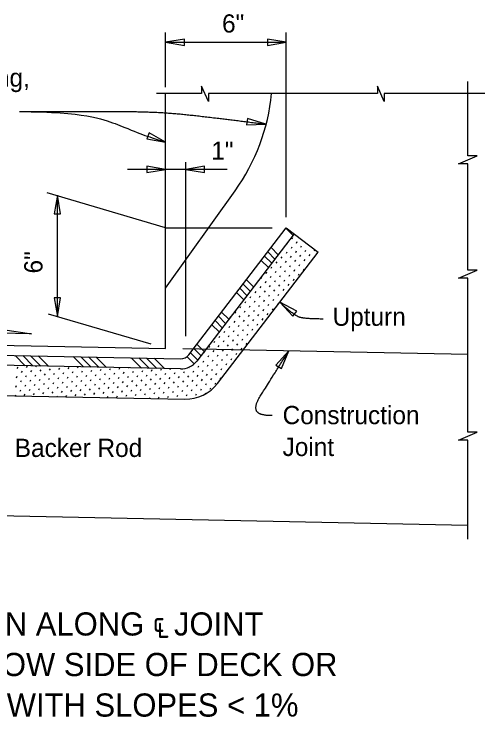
# Model space of a CAD drawing. Extents: x -7.9 to 27, y -3.1 to 14.6.
# Drawn here: x 12.683 to 14.635, y 7.031 to 9.943 of the extents above; entities that cross this region are included whole.
import ezdxf

# ---------------------------------------------------------------- set-up
doc = ezdxf.new("R2010")
doc.units = 0
for name, color, linetype in [('Border', 7, 'Continuous'), ('Patterning', 7, 'Continuous'), ('PlotBorder_dp', 7, 'Continuous'), ('SupstrConc_h', 7, 'Continuous'), ('TextMisc', 7, 'Continuous')]:
    doc.layers.add(name, color=color, linetype=linetype)

msp = doc.modelspace()

# ---------------------------------------------------------------- linework, layer by layer
at = {"layer": 'Patterning'}
for p, q in [((13.3108, 8.8076), (13.3108, 9.6137)), ((13.3108, 8.8076), (13.5991, 9.2112)), ((13.3108, 8.5576), (13.3108, 8.8076)), ((11.429, 8.5953), (13.3109, 8.5576)), ((14.5636, 7.8243), (11.2433, 7.8907))]:
    msp.add_line(p, q, dxfattribs=at)
msp.add_arc((12.9211, 9.6955), 0.8333, 324.4623, 354.3636, dxfattribs=at)
at = {"layer": 'PlotBorder_dp'}
for p, q in [((13.3108, 9.6403), (13.3108, 9.8663)), ((13.8108, 9.101), (13.8108, 9.8663)), ((13.3109, 9.8265), (13.8108, 9.8265)), ((13.3943, 8.6086), (13.3943, 9.3289)), ((13.5659, 9.2993), (13.1524, 9.2993)), ((13.3108, 9.0576), (12.8193, 9.202)), ((12.8626, 8.6893), (12.8626, 9.1931)), ((13.3108, 9.0576), (13.7523, 9.0576)), ((13.2505, 8.5753), (12.8258, 8.7001))]:
    msp.add_line(p, q, dxfattribs=at)
for points in [[(13.3108, 9.8265), (13.3889, 9.8133), (13.3889, 9.8398)], [(13.8108, 9.8265), (13.7327, 9.8398), (13.7327, 9.8133)], [(13.7257, 9.487), (13.65, 9.5101), (13.6466, 9.4839)], [(13.3108, 9.4117), (13.2421, 9.4512), (13.233, 9.4263)], [(13.3108, 9.2993), (13.2327, 9.3125), (13.2327, 9.2861)], [(13.3941, 9.2993), (13.4722, 9.2861), (13.4722, 9.3125)], [(12.8625, 9.1931), (12.8493, 9.115), (12.8757, 9.115)], [(12.8625, 8.6893), (12.8757, 8.7674), (12.8493, 8.7674)], [(13.7846, 8.7493), (13.8388, 8.6916), (13.8548, 8.7127)], [(13.8212, 8.5474), (13.7685, 8.4883), (13.7909, 8.4742)]]:
    msp.add_lwpolyline(points, close=True, dxfattribs=at)
for points in [[(14.0016, 9.6137), (13.4885, 9.6137), (13.4885, 9.5806), (13.4602, 9.6446), (13.4602, 9.6137), (13.2727, 9.6137)], [(14.6346, 9.6137), (14.2175, 9.6137), (14.2175, 9.5806), (14.1891, 9.6446), (14.1891, 9.6137), (14.0016, 9.6137)], [(14.5635, 9.1117), (14.5635, 9.3223), (14.5248, 9.3223), (14.5635, 9.3391), (14.6023, 9.356), (14.5635, 9.356), (14.5635, 9.6632)], [(14.5635, 8.5716), (14.5635, 8.8485), (14.5248, 8.8485), (14.5635, 8.8654), (14.6023, 8.8823), (14.5635, 8.8823), (14.5635, 9.1117)], [(12.3148, 8.6261), (12.3513, 8.6785), (12.7548, 8.6186), (11.5512, 8.6426)], [(14.5635, 7.7673), (14.5635, 8.1769), (14.5248, 8.1769), (14.5635, 8.1937), (14.6023, 8.2106), (14.5635, 8.2106), (14.5635, 8.5716)]]:
    msp.add_lwpolyline(points, dxfattribs=at)
for points, degree in [([(12.7059, 9.5391), (12.9753, 9.5376), (13.1215, 9.4824), (13.2211, 9.4402), (13.2642, 9.4283), (13.3108, 9.4118)], 3), ([(12.7059, 9.5391), (13.0232, 9.5391), (13.2819, 9.5391), (13.535, 9.5116), (13.7257, 9.487)], 2), ([(13.9636, 8.6795), (13.892, 8.6795), (13.8437, 8.693), (13.7846, 8.7493)], 2), ([(13.7533, 8.2791), (13.6947, 8.2791), (13.6796, 8.3226), (13.7287, 8.4), (13.8213, 8.5474)], 2)]:
    msp.add_open_spline(points, degree=degree, dxfattribs=at)
at = {"layer": 'SupstrConc_h'}
msp.add_line((14.5636, 8.5325), (13.3824, 8.5562), dxfattribs=at)
at = {"layer": 'TextMisc'}
for p, q in [((13.4071, 8.531), (13.8109, 9.0576)), ((13.844, 9.0322), (13.4402, 8.5055)), ((13.8096, 9.056), (13.8394, 9.0262)), ((13.8109, 9.0576), (13.9432, 8.9562)), ((13.8357, 9.0122), (13.8389, 9.0178)), ((13.8534, 8.9945), (13.8567, 9.0001)), ((13.7479, 8.9755), (13.7777, 8.9458)), ((13.8148, 8.9913), (13.818, 8.9969)), ((13.8325, 8.9735), (13.8357, 8.9791)), ((13.8711, 8.9768), (13.8744, 8.9824)), ((13.9098, 8.98), (13.9105, 8.9812)), ((13.5266, 8.4128), (13.9432, 8.9562)), ((13.7344, 8.9579), (13.7641, 8.9281)), ((13.8115, 8.9526), (13.8148, 8.9582)), ((13.8502, 8.9558), (13.8534, 8.9614)), ((13.8679, 8.9381), (13.8711, 8.9437)), ((13.8889, 8.9591), (13.8921, 8.9647)), ((13.9066, 8.9414), (13.9098, 8.947)), ((13.9275, 8.9623), (13.9299, 8.9664)), ((13.7073, 8.9225), (13.7371, 8.8928)), ((13.7209, 8.9402), (13.7506, 8.9104)), ((13.7696, 8.9107), (13.7728, 8.9163)), ((13.7906, 8.9316), (13.7938, 8.9372)), ((13.8083, 8.9139), (13.8115, 8.9195)), ((13.8292, 8.9349), (13.8325, 8.9405)), ((13.8469, 8.9172), (13.8502, 8.9228)), ((13.8856, 8.9204), (13.8889, 8.926)), ((13.7486, 8.8897), (13.7519, 8.8953)), ((13.7873, 8.893), (13.7906, 8.8986)), ((13.826, 8.8962), (13.8292, 8.9018)), ((13.8437, 8.8785), (13.8469, 8.8841)), ((13.8647, 8.8995), (13.8679, 8.905)), ((13.8824, 8.8817), (13.8856, 8.8873)), ((13.7277, 8.8688), (13.7309, 8.8744)), ((13.7454, 8.8511), (13.7486, 8.8567)), ((13.7664, 8.872), (13.7696, 8.8776)), ((13.7841, 8.8543), (13.7873, 8.8599)), ((13.805, 8.8753), (13.8083, 8.8809)), ((13.8227, 8.8575), (13.826, 8.8631)), ((13.8614, 8.8608), (13.8647, 8.8664)), ((13.6456, 8.8421), (13.6754, 8.8123)), ((13.7067, 8.8478), (13.71, 8.8534)), ((13.7244, 8.8301), (13.7277, 8.8357)), ((13.7631, 8.8333), (13.7664, 8.8389)), ((13.8018, 8.8366), (13.805, 8.8422)), ((13.8405, 8.8398), (13.8437, 8.8454)), ((13.6185, 8.8067), (13.6483, 8.777)), ((13.6321, 8.8244), (13.6618, 8.7947)), ((13.7035, 8.8091), (13.7067, 8.8147)), ((13.7212, 8.7914), (13.7244, 8.797)), ((13.7422, 8.8124), (13.7454, 8.818)), ((13.7599, 8.7947), (13.7631, 8.8003)), ((13.7808, 8.8156), (13.7841, 8.8212)), ((13.7985, 8.7979), (13.8018, 8.8035)), ((13.8195, 8.8189), (13.8227, 8.8245)), ((13.605, 8.7891), (13.6347, 8.7593)), ((13.6616, 8.7672), (13.6648, 8.7728)), ((13.6825, 8.7882), (13.6858, 8.7938)), ((13.7003, 8.7705), (13.7035, 8.7761)), ((13.7389, 8.7737), (13.7422, 8.7793)), ((13.7776, 8.777), (13.7808, 8.7826)), ((13.6406, 8.7463), (13.6439, 8.7519)), ((13.6793, 8.7495), (13.6825, 8.7551)), ((13.718, 8.7528), (13.7212, 8.7584)), ((13.7357, 8.735), (13.7389, 8.7406)), ((13.7566, 8.756), (13.7599, 8.7616)), ((13.7744, 8.7383), (13.7776, 8.7439)), ((13.5987, 8.7044), (13.602, 8.71)), ((13.6197, 8.7253), (13.6229, 8.7309)), ((13.6374, 8.7076), (13.6406, 8.7132)), ((13.6583, 8.7286), (13.6616, 8.7342)), ((13.6761, 8.7109), (13.6793, 8.7164)), ((13.697, 8.7318), (13.7003, 8.7374)), ((13.7147, 8.7141), (13.718, 8.7197)), ((13.7534, 8.7173), (13.7566, 8.7229)), ((13.5298, 8.6909), (13.5595, 8.6612)), ((13.5433, 8.7086), (13.573, 8.6789)), ((13.5778, 8.6834), (13.581, 8.689)), ((13.6164, 8.6867), (13.6197, 8.6923)), ((13.6551, 8.6899), (13.6583, 8.6955)), ((13.6938, 8.6931), (13.697, 8.6987)), ((13.7115, 8.6754), (13.7147, 8.681)), ((13.7324, 8.6964), (13.7357, 8.702)), ((13.5027, 8.6556), (13.5324, 8.6259)), ((13.5162, 8.6733), (13.546, 8.6435)), ((13.5955, 8.6657), (13.5987, 8.6713)), ((13.6132, 8.648), (13.6164, 8.6536)), ((13.6341, 8.6689), (13.6374, 8.6745)), ((13.6519, 8.6512), (13.6551, 8.6568)), ((13.6728, 8.6722), (13.6761, 8.6778)), ((13.6905, 8.6545), (13.6938, 8.6601)), ((13.5536, 8.6238), (13.5568, 8.6294)), ((13.5745, 8.6447), (13.5778, 8.6503)), ((13.5922, 8.627), (13.5955, 8.6326)), ((13.6309, 8.6303), (13.6341, 8.6359)), ((13.6696, 8.6335), (13.6728, 8.6391)), ((13.5326, 8.6028), (13.5359, 8.6084)), ((13.5713, 8.6061), (13.5745, 8.6117)), ((13.589, 8.5884), (13.5922, 8.594)), ((13.6099, 8.6093), (13.6132, 8.6149)), ((13.6277, 8.5916), (13.6309, 8.5972)), ((13.6486, 8.6126), (13.6519, 8.6182)), ((13.6669, 8.5959), (13.6696, 8.6004)), ((13.441, 8.5752), (13.4707, 8.5454)), ((13.4907, 8.5609), (13.4939, 8.5665)), ((13.5117, 8.5819), (13.5149, 8.5875)), ((13.5294, 8.5642), (13.5326, 8.5698)), ((13.5503, 8.5851), (13.5536, 8.5907)), ((13.568, 8.5674), (13.5713, 8.573)), ((13.6067, 8.5706), (13.6099, 8.5762)), ((13.6454, 8.5739), (13.6486, 8.5795)), ((11.2433, 8.5573), (13.3732, 8.5146)), ((13.4139, 8.5398), (13.4436, 8.5101)), ((13.4274, 8.5575), (13.4572, 8.5277)), ((13.4697, 8.54), (13.473, 8.5456)), ((13.5084, 8.5432), (13.5117, 8.5488)), ((13.5471, 8.5464), (13.5503, 8.552)), ((13.5648, 8.5287), (13.568, 8.5343)), ((13.5858, 8.5497), (13.589, 8.5553)), ((13.6035, 8.532), (13.6067, 8.5376)), ((13.6244, 8.5529), (13.6277, 8.5585)), ((13.3724, 8.4729), (11.2433, 8.5156)), ((12.6868, 8.5284), (12.7294, 8.4858)), ((12.7187, 8.5277), (12.7612, 8.4852)), ((12.7505, 8.5271), (12.7931, 8.4845)), ((12.7823, 8.5265), (12.8249, 8.4839)), ((12.9274, 8.5236), (12.97, 8.481)), ((12.9593, 8.5229), (13.0018, 8.4804)), ((12.9911, 8.5223), (13.0337, 8.4797)), ((13.0229, 8.5217), (13.0655, 8.4791)), ((13.168, 8.5187), (13.2106, 8.4762)), ((13.1998, 8.5181), (13.2424, 8.4755)), ((13.2317, 8.5175), (13.2742, 8.4749)), ((13.2635, 8.5168), (13.3061, 8.4743)), ((13.3989, 8.5236), (13.4278, 8.4948)), ((13.4665, 8.5013), (13.4697, 8.5069)), ((13.4875, 8.5223), (13.4907, 8.5279)), ((13.5052, 8.5045), (13.5084, 8.5101)), ((13.5261, 8.5255), (13.5294, 8.5311)), ((13.5438, 8.5078), (13.5471, 8.5134)), ((13.5825, 8.511), (13.5858, 8.5166)), ((12.6963, 8.4751), (12.6996, 8.4807)), ((12.735, 8.4784), (12.7383, 8.484)), ((12.7737, 8.4816), (12.7756, 8.4849)), ((12.8687, 8.4704), (12.872, 8.476)), ((12.9074, 8.4736), (12.9107, 8.4792)), ((12.9461, 8.4769), (12.9487, 8.4814)), ((12.9847, 8.4801), (12.9851, 8.4807)), ((13.1185, 8.4721), (13.1217, 8.4777)), ((13.1571, 8.4754), (13.1582, 8.4772)), ((13.4069, 8.4771), (13.4089, 8.4806)), ((13.4455, 8.4803), (13.4488, 8.4859)), ((13.4842, 8.4836), (13.4875, 8.4892)), ((13.5229, 8.4868), (13.5261, 8.4924)), ((13.5616, 8.4901), (13.5648, 8.4957)), ((12.7141, 8.4574), (12.7173, 8.463)), ((12.7527, 8.4607), (12.756, 8.4663)), ((12.7704, 8.443), (12.7737, 8.4486)), ((12.7914, 8.4639), (12.7946, 8.4695)), ((12.8091, 8.4462), (12.8124, 8.4518)), ((12.8301, 8.4672), (12.8333, 8.4728)), ((12.8478, 8.4494), (12.851, 8.455)), ((12.8865, 8.4527), (12.8897, 8.4583)), ((12.9251, 8.4559), (12.9284, 8.4615)), ((12.9638, 8.4592), (12.967, 8.4648)), ((12.9815, 8.4415), (12.9847, 8.447)), ((13.0025, 8.4624), (13.0057, 8.468)), ((13.0202, 8.4447), (13.0234, 8.4503)), ((13.0411, 8.4656), (13.0444, 8.4712)), ((13.0588, 8.4479), (13.0621, 8.4535)), ((13.0798, 8.4689), (13.083, 8.4745)), ((13.0975, 8.4512), (13.1008, 8.4568)), ((13.1362, 8.4544), (13.1394, 8.46)), ((13.1749, 8.4577), (13.1781, 8.4633)), ((13.2135, 8.4609), (13.2168, 8.4665)), ((13.2312, 8.4432), (13.2345, 8.4488)), ((13.2522, 8.4641), (13.2554, 8.4697)), ((13.2699, 8.4464), (13.2732, 8.452)), ((13.2909, 8.4674), (13.2941, 8.473)), ((13.3086, 8.4497), (13.3118, 8.4553)), ((13.3295, 8.4706), (13.3314, 8.4738)), ((13.3473, 8.4529), (13.3505, 8.4585)), ((13.3859, 8.4561), (13.3892, 8.4617)), ((13.4246, 8.4594), (13.4278, 8.465)), ((13.4423, 8.4417), (13.4455, 8.4473)), ((13.4633, 8.4626), (13.4665, 8.4682)), ((13.481, 8.4449), (13.4842, 8.4505)), ((13.5019, 8.4659), (13.5052, 8.4715)), ((13.5196, 8.4482), (13.5229, 8.4538)), ((13.5406, 8.4691), (13.5438, 8.4747)), ((12.6931, 8.4365), (12.6963, 8.4421)), ((12.7108, 8.4188), (12.7141, 8.4244)), ((12.7318, 8.4397), (12.735, 8.4453)), ((12.7495, 8.422), (12.7527, 8.4276)), ((12.7882, 8.4252), (12.7914, 8.4308)), ((12.8268, 8.4285), (12.8301, 8.4341)), ((12.8655, 8.4317), (12.8687, 8.4373)), ((12.8832, 8.414), (12.8865, 8.4196)), ((12.9042, 8.435), (12.9074, 8.4406)), ((12.9219, 8.4173), (12.9251, 8.4229)), ((12.9428, 8.4382), (12.9461, 8.4438)), ((12.9606, 8.4205), (12.9638, 8.4261)), ((12.9992, 8.4237), (13.0025, 8.4293)), ((13.0379, 8.427), (13.0411, 8.4326)), ((13.0766, 8.4302), (13.0798, 8.4358)), ((13.0943, 8.4125), (13.0975, 8.4181)), ((13.1152, 8.4335), (13.1185, 8.4391)), ((13.1329, 8.4157), (13.1362, 8.4213)), ((13.1539, 8.4367), (13.1571, 8.4423)), ((13.1716, 8.419), (13.1749, 8.4246)), ((13.1926, 8.4399), (13.1958, 8.4455)), ((13.2103, 8.4222), (13.2135, 8.4278)), ((13.249, 8.4255), (13.2522, 8.4311)), ((13.2876, 8.4287), (13.2909, 8.4343)), ((13.3263, 8.4319), (13.3295, 8.4375)), ((13.344, 8.4142), (13.3473, 8.4198)), ((13.365, 8.4352), (13.3682, 8.4408)), ((13.3827, 8.4175), (13.3859, 8.4231)), ((13.4036, 8.4384), (13.4069, 8.444)), ((13.4214, 8.4207), (13.4246, 8.4263)), ((13.46, 8.424), (13.4633, 8.4296)), ((13.4987, 8.4272), (13.5019, 8.4328)), ((13.5374, 8.4304), (13.5406, 8.436)), ((11.2433, 8.3905), (13.3909, 8.3476)), ((12.6899, 8.3978), (12.6931, 8.4034)), ((12.7285, 8.4011), (12.7318, 8.4066)), ((12.7462, 8.3833), (12.7495, 8.3889)), ((12.7672, 8.4043), (12.7704, 8.4099)), ((12.7849, 8.3866), (12.7882, 8.3922)), ((12.8059, 8.4075), (12.8091, 8.4131)), ((12.8236, 8.3898), (12.8268, 8.3954)), ((12.8445, 8.4108), (12.8478, 8.4164)), ((12.8623, 8.3931), (12.8655, 8.3987)), ((12.9009, 8.3963), (12.9042, 8.4019)), ((12.9396, 8.3995), (12.9428, 8.4051)), ((12.9783, 8.4028), (12.9815, 8.4084)), ((12.996, 8.3851), (12.9992, 8.3907)), ((13.0169, 8.406), (13.0202, 8.4116)), ((13.0347, 8.3883), (13.0379, 8.3939)), ((13.0556, 8.4093), (13.0588, 8.4149)), ((13.0733, 8.3915), (13.0766, 8.3971)), ((13.112, 8.3948), (13.1152, 8.4004)), ((13.1507, 8.398), (13.1539, 8.4036)), ((13.1893, 8.4013), (13.1926, 8.4069)), ((13.207, 8.3836), (13.2103, 8.3892)), ((13.228, 8.4045), (13.2312, 8.4101)), ((13.2457, 8.3868), (13.249, 8.3924)), ((13.2667, 8.4078), (13.2699, 8.4134)), ((13.2844, 8.39), (13.2876, 8.3956)), ((13.3053, 8.411), (13.3086, 8.4166)), ((13.3231, 8.3933), (13.3263, 8.3989)), ((13.3617, 8.3965), (13.365, 8.4021)), ((13.4004, 8.3998), (13.4036, 8.4054)), ((13.4391, 8.403), (13.4423, 8.4086)), ((13.4568, 8.3853), (13.46, 8.3909)), ((13.4777, 8.4062), (13.481, 8.4118)), ((13.4954, 8.3885), (13.4987, 8.3941)), ((13.5164, 8.4095), (13.5196, 8.4151)), ((12.6881, 8.3616), (12.6899, 8.3647)), ((12.7076, 8.3801), (12.7108, 8.3857)), ((12.7253, 8.3624), (12.7285, 8.368)), ((12.764, 8.3656), (12.7672, 8.3712)), ((12.8026, 8.3689), (12.8059, 8.3745)), ((12.8413, 8.3721), (12.8445, 8.3777)), ((12.8612, 8.3582), (12.8623, 8.36)), ((12.88, 8.3753), (12.8832, 8.3809)), ((12.8977, 8.3576), (12.9009, 8.3632)), ((12.9186, 8.3786), (12.9219, 8.3842)), ((12.9364, 8.3609), (12.9396, 8.3665)), ((12.9573, 8.3818), (12.9606, 8.3874)), ((12.975, 8.3641), (12.9783, 8.3697)), ((13.0137, 8.3674), (13.0169, 8.373)), ((13.0524, 8.3706), (13.0556, 8.3762)), ((13.091, 8.3738), (13.0943, 8.3794)), ((13.1088, 8.3561), (13.112, 8.3617)), ((13.1297, 8.3771), (13.1329, 8.3827)), ((13.1474, 8.3594), (13.1507, 8.365)), ((13.1684, 8.3803), (13.1716, 8.3859)), ((13.1861, 8.3626), (13.1893, 8.3682)), ((13.2248, 8.3658), (13.228, 8.3714)), ((13.2634, 8.3691), (13.2667, 8.3747)), ((13.3021, 8.3723), (13.3053, 8.3779)), ((13.3198, 8.3546), (13.3231, 8.3602)), ((13.3408, 8.3756), (13.344, 8.3812)), ((13.3585, 8.3579), (13.3617, 8.3634)), ((13.3794, 8.3788), (13.3827, 8.3844)), ((13.3972, 8.3611), (13.4004, 8.3667)), ((13.4181, 8.382), (13.4214, 8.3876)), ((13.4358, 8.3643), (13.4391, 8.3699)), ((13.475, 8.3684), (13.4777, 8.3732)), ((13.0343, 8.3547), (13.0347, 8.3552)), ((13.0707, 8.354), (13.0733, 8.3585)), ((13.2438, 8.3505), (13.2457, 8.3537)), ((13.2811, 8.3514), (13.2844, 8.357))]:
    msp.add_line(p, q, dxfattribs=at)
for centre, radius in [((13.3741, 8.5562), 0.0833), ((13.374, 8.5563), 0.0417), ((13.3943, 8.5142), 0.1667)]:
    msp.add_arc(centre, radius, 268.8533, 322.5215, dxfattribs=at)

# ---------------------------------------------------------------- texts
at = {"layer": 'Border'}
for s, p in [('6"', (13.5449, 9.8665)), ('1"', (13.5001, 9.3393)), ('Upturn', (14.0031, 8.6514)), ('Foam Backer Rod', (12.3992, 8.1079))]:
    msp.add_text(s, height=0.0756, dxfattribs=at).set_placement(p)
msp.add_text('6"', height=0.0756, rotation=90, dxfattribs=at).set_placement((12.8005, 8.8683))
at = {"layer": 'PlotBorder_dp'}
for s, height, p in [('Face of Traffic Railing, ', 0.0756, (11.737, 9.642)), ('Construction ', 0.0756, (13.7959, 8.2438)), ('Joint', 0.0756, (13.7959, 8.1118)), ('PARTIAL SECTION ALONG ℄ JOINT', 0.096, (11.5958, 7.368)), ('JOINT TREATMENT AT LOW SIDE OF DECK OR', 0.096, (11.1347, 7.2)), ('HIGH SIDE OF DECK WITH SLOPES < 1%', 0.096, (11.3543, 7.032))]:
    msp.add_text(s, height=height, dxfattribs=at).set_placement(p)

doc.saveas('drawing.dxf')
